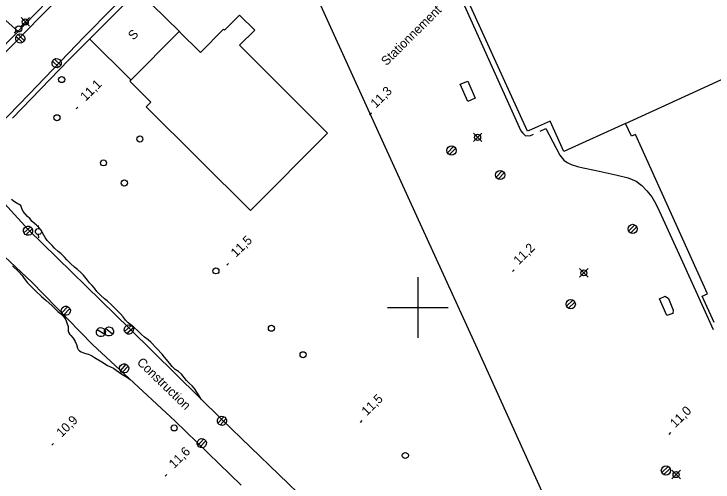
# Model space of a CAD drawing. Extents: x 381879 to 384696, y 5564785 to 5567594.
# Drawn here: x 383466.9 to 383697.3, y 5565942.5 to 5566096.7 of the extents above; entities that cross this region are included whole.
import ezdxf

# ---------------------------------------------------------------- set-up
doc = ezdxf.new("R2010")
doc.units = 0
for name, color, linetype in [('Niveau 1', 7, 'Continuous'), ('Niveau 19', 7, 'Continuous'), ('Niveau 21', 7, 'Continuous'), ('Niveau 22', 7, 'Continuous'), ('Niveau 3', 7, 'Continuous'), ('Niveau 31', 7, 'Continuous'), ('Niveau 36', 7, 'Continuous'), ('Niveau 52', 7, 'Continuous'), ('Niveau 61', 7, 'Continuous')]:
    doc.layers.add(name, color=color, linetype=linetype)

msp = doc.modelspace()

# ---------------------------------------------------------------- linework, layer by layer
at = {"layer": 'Niveau 1'}
for points in [[(383527.94, 5565970.91), (383526.45, 5565973.31), (383525.66, 5565974.19), (383524.67, 5565975.01), (383523.81, 5565975.87), (383523.01, 5565976.93), (383522.11, 5565977.98), (383521.13, 5565978.85), (383520.07, 5565979.59), (383519.04, 5565980.51), (383518.28, 5565981.49), (383516.58, 5565983.61), (383515.72, 5565984.54), (383513.88, 5565986.57), (383512.06, 5565988.53), (383511.1, 5565989.33), (383509.97, 5565990.15), (383508.91, 5565991.09), (383507.89, 5565992.11), (383506.42, 5565993.51), (383505.49, 5565994.25), (383504.51, 5565994.91), (383503.67, 5565995.76), (383502.88, 5565996.84), (383501.99, 5565997.85), (383500.59, 5565999.31), (383499.1, 5566000.79), (383497.66, 5566002.13), (383496.75, 5566002.87), (383495.43, 5566004.02), (383494.25, 5566005.18), (383493.48, 5566006.28), (383492.68, 5566007.24), (383491.8, 5566008.11), (383491.15, 5566008.94), (383489.81, 5566010.56), (383488.98, 5566011.45), (383487.83, 5566012.51), (383486.85, 5566013.28), (383485.59, 5566014.41), (383484.33, 5566015.67), (383483.6, 5566016.51), (383482.45, 5566017.67), (383481.54, 5566018.37), (383480.29, 5566019.53), (383479.48, 5566020.43), (383478.63, 5566021.21), (383477.87, 5566022.05), (383477.26, 5566023.06), (383475.79, 5566025.53), (383475.08, 5566026.32), (383474.3, 5566027.03), (383472.95, 5566028.32), (383472.12, 5566029.25), (383471.35, 5566029.94), (383470.64, 5566030.77), (383470.01, 5566031.63), (383469.54, 5566032.58), (383469.14, 5566033.56), (383468.65, 5566033.88), (383468.18, 5566034.08), (383467.13, 5566034.75), (383466.14, 5566035.55)], [(383466.47, 5566013.71), (383468.52, 5566011.71), (383469.59, 5566010.48), (383470.25, 5566009.54), (383471.41, 5566008.11), (383472.3, 5566007.2), (383474.15, 5566005.37), (383476.02, 5566003.58), (383477.49, 5566002.32), (383479.36, 5566000.65), (383480.21, 5565999.8), (383481.42, 5565998.67), (383482.27, 5565998.03), (383483.41, 5565996.92), (383484.01, 5565995.94), (383484.38, 5565994.96), (383484.76, 5565993.69), (383484.8, 5565993.15), (383484.77, 5565992.13), (383484.96, 5565991.6), (383485.3, 5565991.09), (383485.67, 5565990.73), (383486.46, 5565989.85), (383487.12, 5565988.75), (383487.54, 5565987.72), (383487.84, 5565986.56), (383488.07, 5565986.11), (383488.47, 5565985.7), (383489.02, 5565985.37), (383490.22, 5565984.88), (383491.35, 5565984.56), (383492.48, 5565984.13), (383493.47, 5565983.5), (383495.89, 5565982.07), (383497.72, 5565980.87), (383498.69, 5565980.39), (383499.73, 5565979.99), (383500.63, 5565979.34), (383502.5, 5565978.05), (383503.82, 5565977.22), (383504.74, 5565976.54), (383505.25, 5565976.23)], [(383528.64, 5565969.75), (383527.94, 5565970.91)]]:
    msp.add_lwpolyline(points, dxfattribs=at)
at = {"layer": 'Niveau 19'}
msp.add_lwpolyline([(383468.27, 5566091), (383468.24, 5566091.03), (383453.44, 5566104.08)], dxfattribs=at)
at = {"layer": 'Niveau 21'}
for points in [[(383576.28, 5566159.65), (383565.4, 5566154.6), (383555.08, 5566149.31), (383547.78, 5566144.61), (383540.75, 5566139.32), (383534.05, 5566133.64), (383523.68, 5566123.66), (383508.73, 5566108.16), (383490.03, 5566089.16), (383471.9, 5566070.2), (383461.53, 5566059.56)], [(383442.2, 5566061.7), (383475.8, 5566095.9), (383490.9, 5566111.1)], [(383685.83, 5565816.95), (383644.43, 5565857.27), (383609.39, 5565891.6), (383563.54, 5565935.93), (383535.54, 5565962.94), (383505.13, 5565992.93), (383471.65, 5566025.61), (383456.99, 5566041.58), (383455.1, 5566045.7), (383454.63, 5566049.64), (383456.67, 5566054.42), (383461.53, 5566059.56)], [(383433.96, 5566031.14), (383438.19, 5566033.74), (383444.95, 5566033), (383453.18, 5566026.7), (383472.86, 5566008.3), (383492.8, 5565987.78), (383520.05, 5565962.5), (383541.82, 5565941.4)]]:
    msp.add_lwpolyline(points, dxfattribs=at)
at = {"layer": 'Niveau 22'}
for points in [[(383414.56, 5566036.19), (383435.49, 5566057.53), (383462.29, 5566084.88), (383490, 5566113.26), (383511.14, 5566134.8)], [(383485, 5566081.5), (383487.6, 5566084.2), (383506.7, 5566103.3), (383526.81, 5566124.43)], [(383607.6, 5566120.2), (383606.7, 5566118.9), (383606.8, 5566118.1), (383607.8, 5566116.2), (383634, 5566058.2), (383634.6, 5566057.4), (383635.5, 5566056.5), (383636.3, 5566056.6), (383636.9, 5566056.5), (383638.1, 5566057.1)], [(383466.4, 5566062.3), (383485, 5566081.5)], [(383640.3, 5566058.1), (383642.2, 5566058.9), (383646.8, 5566050.1), (383648.1, 5566048.5), (383649.2, 5566047.7), (383650.6, 5566047.1), (383652.6, 5566046.4), (383654.5, 5566046), (383658.8, 5566045.1), (383665.7, 5566043.6), (383669.3, 5566042.7), (383672.01, 5566041.54), (383673.8, 5566040.2), (383675.53, 5566038.41), (383677.1, 5566036.37), (383677.97, 5566034.92), (383679.04, 5566032.98), (383686.74, 5566016.21), (383697.36, 5565992.67)]]:
    msp.add_lwpolyline(points, dxfattribs=at)
at = {"layer": 'Niveau 3'}
for p, q in [((383487.37, 5566065.38), (383487.94, 5566065.95)), ((383584.13, 5566063.49), (383584.7, 5566064.06)), ((383537.03, 5566013.86), (383537.6, 5566014.43)), ((383631.23, 5566011.82), (383631.8, 5566012.39)), ((383581.15, 5565962.11), (383581.72, 5565962.68)), ((383682.8, 5565958.16), (383683.37, 5565958.73)), ((383479.41, 5565954.6), (383479.98, 5565955.17)), ((383516.77, 5565944.42), (383517.34, 5565944.99))]:
    msp.add_line(p, q, dxfattribs=at)
at = {"layer": 'Niveau 31'}
for points in [[(383697.7, 5565995), (383693.7, 5566003.7), (383695.5, 5566004.5), (383671.7, 5566056.9), (383670.4, 5566056.4), (383668.5, 5566060.6), (383648.1, 5566051.4), (383643.6, 5566061.4), (383639.7, 5566059.6), (383637.5, 5566058.6), (383636.2, 5566058), (383612.8, 5566109.4)], [(383668.5, 5566060.6), (383731.24, 5566089.3)]]:
    msp.add_lwpolyline(points, dxfattribs=at)
msp.add_lwpolyline([(383544.87, 5566031.87), (383510.54, 5566066.03), (383512.08, 5566067.57), (383505.09, 5566074.54), (383521.4, 5566090.93), (383528.35, 5566084.01), (383535.93, 5566091.62), (383536.28, 5566091.27), (383541.3, 5566096.31), (383546.27, 5566091.36), (383541.26, 5566086.33), (383570.3, 5566057.42)], close=True, dxfattribs=at)
at = {"layer": 'Niveau 36'}
for p, q in [((383472.07, 5566095.45), (383469.25, 5566092.63)), ((383472.07, 5566092.63), (383469.25, 5566095.45)), ((383469.9, 5566093.17), (383469.19, 5566092.47)), ((383467.08, 5566090.34), (383467.77, 5566091.06)), ((383467.64, 5566089.29), (383469.7, 5566087.25)), ((383470.34, 5566087.91), (383468.28, 5566089.95)), ((383479.62, 5566081.1), (383481.73, 5566079.11)), ((383482.34, 5566079.8), (383480.23, 5566081.79)), ((383621.13, 5566057.42), (383618.31, 5566054.6)), ((383621.13, 5566054.6), (383618.31, 5566057.42)), ((383611.8, 5566053), (383609.74, 5566050.96)), ((383610.4, 5566050.32), (383612.46, 5566052.36)), ((383627.84, 5566044.96), (383625.78, 5566042.92)), ((383626.44, 5566042.28), (383628.5, 5566044.32)), ((383474.92, 5566026.96), (383474.98, 5566025.96)), ((383671.49, 5566027.18), (383669.43, 5566025.14)), ((383472.32, 5566026.57), (383470.18, 5566024.61)), ((383470.82, 5566023.95), (383472.96, 5566025.91)), ((383670.09, 5566024.5), (383672.15, 5566026.54)), ((383475.08, 5566022.96), (383475.05, 5566023.96)), ((383656.15, 5566012.78), (383653.33, 5566009.96)), ((383656.15, 5566009.96), (383653.33, 5566012.78)), ((383651.1, 5566002.39), (383649.04, 5566000.35)), ((383649.7, 5565999.71), (383651.76, 5566001.75)), ((383484.66, 5566000.28), (383482.68, 5565998.16)), ((383483.36, 5565997.54), (383485.34, 5565999.66)), ((383496.86, 5565991.07), (383494.3, 5565992.61)), ((383499.42, 5565991.13), (383497.08, 5565992.99)), ((383505.59, 5565993.98), (383503.38, 5565992.1)), ((383503.99, 5565991.42), (383506.2, 5565993.3)), ((383503.84, 5565981.29), (383501.9, 5565979.14)), ((383502.6, 5565978.53), (383504.54, 5565980.68)), ((383536.11, 5565963.99), (383534.15, 5565961.85)), ((383534.85, 5565961.25), (383536.81, 5565963.39)), ((383529.44, 5565956.65), (383527.49, 5565954.51)), ((383528.18, 5565953.91), (383530.13, 5565956.05)), ((383682.47, 5565947.61), (383680.41, 5565945.57)), ((383681.07, 5565944.93), (383683.13, 5565946.97)), ((383686.55, 5565946.34), (383683.73, 5565943.52)), ((383686.55, 5565943.52), (383683.73, 5565946.34))]:
    msp.add_line(p, q, dxfattribs=at)
for centre, radius in [((383470.65, 5566094.04), 1), ((383468.48, 5566091.75), 1), ((383482.65, 5566075.03), 1), ((383481.08, 5566062.47), 1), ((383619.71, 5566056.01), 1), ((383508.41, 5566055.47), 1), ((383611.11, 5566051.66), 1.52), ((383496.43, 5566047.61), 1), ((383627.15, 5566043.62), 1.52), ((383503.29, 5566040.97), 1), ((383670.8, 5566025.84), 1.52), ((383533.47, 5566012.03), 1), ((383654.73, 5566011.37), 1), ((383650.41, 5566001.05), 1.52), ((383551.77, 5565993.11), 1), ((383562.19, 5565984.4), 1), ((383519.72, 5565960.29), 1), ((383595.89, 5565951.2), 1), ((383681.78, 5565946.27), 1.52), ((383685.13, 5565944.93), 1)]:
    msp.add_circle(centre, radius, dxfattribs=at)
for centre, major_axis, ratio in [((383468.99, 5566088.59), (1.21, -0.91), 0.999875), ((383480.98, 5566080.46), (-1.22, 0.9), 0.999874), ((383471.56, 5566025.26), (-1.21, 0.91), 0.999875), ((383475.01, 5566024.97), (-0.799, 0.601), 0.999875), ((383484.02, 5565998.91), (-1.21, 0.92), 0.999875), ((383495.57, 5565991.84), (-1.2, 0.9), 0.999873), ((383498.24, 5565992.06), (-1.19, 0.91), 0.999875), ((383504.78, 5565992.7), (1.22, -0.91), 0.999874), ((383503.23, 5565979.91), (-1.21, 0.92), 0.999875), ((383535.47, 5565962.62), (1.21, -0.91), 0.999875), ((383528.82, 5565955.28), (-1.2, 0.92), 0.999875)]:
    msp.add_ellipse(centre, major_axis=major_axis, ratio=ratio, dxfattribs=at)
at = {"layer": 'Niveau 52'}
for points in [[(383674.89, 5565869.41), (383662.2, 5565894.4), (383641, 5565939.2), (383619.7, 5565986.3), (383599.7, 5566030), (383583.1, 5566066.4), (383564.7, 5566107), (383548.5, 5566142.5)], [(383507.71, 5566104.37), (383521.58, 5566090.76)], [(383505.49, 5566074.94), (383491.86, 5566088.46)], [(383618.9, 5566068.9), (383616.48, 5566067.85), (383613.94, 5566073.54), (383616.48, 5566074.51), (383618.9, 5566068.9)], [(383681.51, 5566003.68), (383682.6, 5566002.89), (383684.2, 5565999.09), (383684, 5565997.99), (383682.12, 5565997.33), (383679.71, 5566002.82), (383681.51, 5566003.68)]]:
    msp.add_lwpolyline(points, dxfattribs=at)
at = {"layer": 'Niveau 61'}
for points in [[(383600, 5566010), (383600, 5566000), (383600, 5565990)], [(383590, 5566000), (383600, 5566000), (383610, 5566000)]]:
    msp.add_lwpolyline(points, dxfattribs=at)

# ---------------------------------------------------------------- texts
at = {"layer": 'Niveau 21'}
msp.add_text('Construction', height=3, rotation=315.9996, dxfattribs=at).set_placement((383507.23, 5565981.62))
at = {"layer": 'Niveau 3'}
for s, p in [('11,1', (383490.55, 5566067.77)), ('11,3 ', (383586.2, 5566065.49)), ('11,5', (383540.13, 5566016.32)), ('11,2 ', (383633.3, 5566013.82)), ('11,5 ', (383583.22, 5565964.11)), ('11,0 ', (383684.87, 5565960.16)), ('10,9', (383482.66, 5565957.06)), ('11,6', (383519.72, 5565946.74))]:
    msp.add_text(s, height=3, rotation=44.7717, dxfattribs=at).set_placement(p)
at = {"layer": 'Niveau 52'}
for s, p in [('Stationnement', (383589.69, 5566079.43)), ('S', (383506.29, 5566087.86))]:
    msp.add_text(s, height=3, rotation=44.7717, dxfattribs=at).set_placement(p)

doc.saveas('drawing.dxf')
